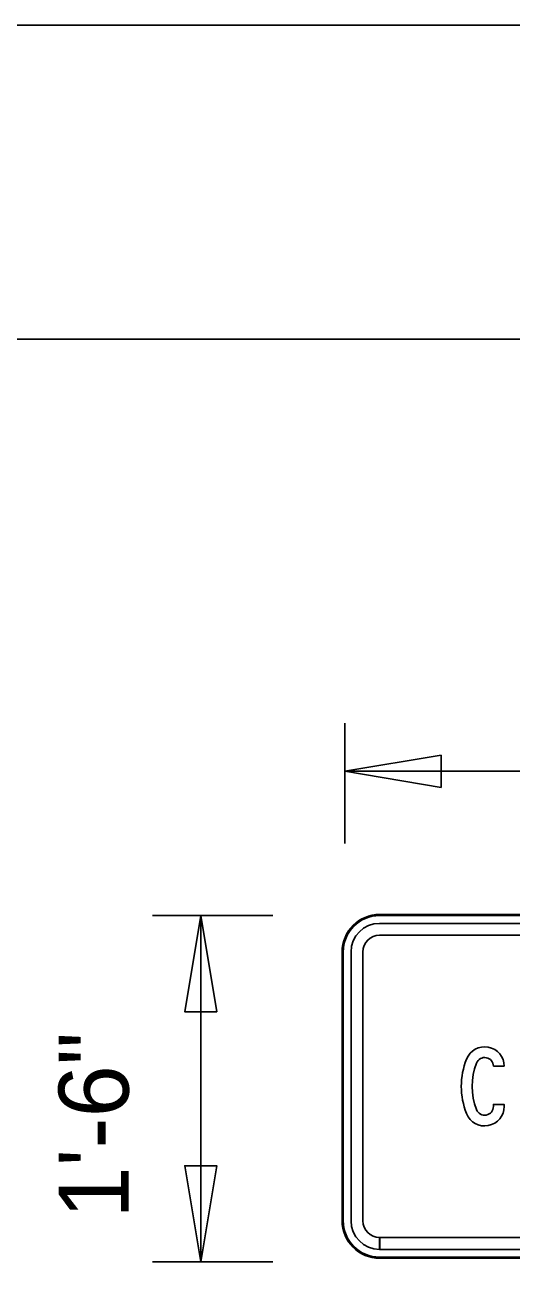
# Model space of a CAD drawing. Extents: x 768137 to 769825, y 651421 to 652521.
# Drawn here: x 769087.4 to 769150.7, y 652123.1 to 652287.3 of the extents above; entities that cross this region are included whole.
import ezdxf

# ---------------------------------------------------------------- set-up
doc = ezdxf.new("R2010")
doc.units = 0
doc.layers.add('Default', color=7, linetype='Continuous')
doc.layers.add('Text', color=7, linetype='Continuous')

msp = doc.modelspace()

# ---------------------------------------------------------------- linework, layer by layer
at = {"layer": 'Default'}
for p, q in [((769128.97, 652180.8), (769128.97, 652196.44)), ((769128.97, 652190.19), (769264.14, 652190.19)), ((769128.97, 652180.8), (769128.97, 652180.8)), ((769257.93, 652171.57), (769133.49, 652171.57)), ((769257.93, 652171.57), (769133.49, 652171.57)), ((769257.93, 652171.57), (769133.49, 652171.57)), ((769257.93, 652171.57), (769133.49, 652171.57)), ((769119.59, 652171.41), (769103.94, 652171.41)), ((769110.2, 652126.36), (769110.2, 652171.41)), ((769119.59, 652171.41), (769119.59, 652171.41)), ((769133.49, 652171.41), (769257.93, 652171.41)), ((769257.93, 652170.4), (769133.49, 652170.4)), ((769257.93, 652170.4), (769133.49, 652170.4)), ((769257.93, 652170.4), (769133.49, 652170.4)), ((769257.93, 652168.85), (769133.49, 652168.85)), ((769133.49, 652168.85), (769257.93, 652168.85)), ((769133.49, 652168.85), (769257.93, 652168.85)), ((769128.59, 652166.68), (769128.59, 652131.72)), ((769128.59, 652166.68), (769128.59, 652131.72)), ((769128.59, 652166.68), (769128.59, 652131.72)), ((769128.59, 652166.68), (769128.59, 652131.72)), ((769128.75, 652131.72), (769128.75, 652166.68)), ((769129.76, 652166.68), (769129.76, 652131.72)), ((769129.76, 652166.68), (769129.76, 652131.72)), ((769129.76, 652166.68), (769129.76, 652131.72)), ((769131.31, 652166.68), (769131.31, 652131.72)), ((769131.31, 652131.72), (769131.31, 652166.68)), ((769131.31, 652131.72), (769131.31, 652166.68)), ((769148.3, 652151.81), (769149.69, 652151.81)), ((769148.3, 652151.81), (769149.69, 652151.81)), ((769148.3, 652151.81), (769149.69, 652151.81)), ((769133.49, 652129.54), (769257.93, 652129.54)), ((769133.49, 652127.99), (769133.49, 652129.54)), ((769133.49, 652127.99), (769133.49, 652129.54)), ((769257.93, 652129.54), (769133.5, 652129.54)), ((769133.5, 652129.54), (769133.5, 652127.99)), ((769257.93, 652129.54), (769133.5, 652129.54)), ((769133.5, 652129.54), (769133.5, 652127.99)), ((769133.49, 652127.99), (769257.93, 652127.99)), ((769133.5, 652127.99), (769257.93, 652127.99)), ((769133.5, 652127.99), (769257.93, 652127.99)), ((769119.59, 652126.36), (769103.94, 652126.36)), ((769119.59, 652126.36), (769119.59, 652126.36)), ((769133.49, 652126.83), (769133.49, 652126.98)), ((769257.93, 652126.98), (769133.49, 652126.98)), ((769133.49, 652126.98), (769133.49, 652126.83)), ((769133.49, 652126.83), (769257.93, 652126.83)), ((769133.49, 652126.83), (769257.93, 652126.83)), ((769133.49, 652126.83), (769257.93, 652126.83)), ((769133.49, 652126.83), (769257.93, 652126.83))]:
    msp.add_line(p, q, dxfattribs=at)
for points in [[(769128.97, 652190.19), (769141.49, 652188.1), (769141.49, 652192.27)], [(769110.2, 652171.41), (769112.29, 652158.9), (769108.11, 652158.9)], [(769110.2, 652126.36), (769112.29, 652138.87), (769108.11, 652138.87)]]:
    msp.add_lwpolyline(points, close=True, dxfattribs=at)
msp.add_lwpolyline([(769149.69, 652146.59), (769149.69, 652146.86), (769148.3, 652146.86), (769148.3, 652146.59)], dxfattribs=at)
msp.add_lwpolyline([(769149.69, 652146.59), (769149.69, 652146.86), (769148.3, 652146.86), (769148.3, 652146.59)], dxfattribs=at)
msp.add_lwpolyline([(769149.69, 652146.59), (769149.69, 652146.86), (769148.3, 652146.86), (769148.3, 652146.59)], dxfattribs=at)
for centre, radius, start, end in [((769133.49, 652166.68), 4.89, 90, 180), ((769133.49, 652166.68), 4.89, 90, 180), ((769133.49, 652166.68), 4.89, 90, 180), ((769133.49, 652166.68), 4.89, 90, 180), ((769133.49, 652166.68), 4.74, 90, 180), ((769133.49, 652166.68), 3.73, 90, 180), ((769133.49, 652166.68), 3.73, 90, 180), ((769133.49, 652166.68), 3.73, 90, 180), ((769133.49, 652166.68), 2.18, 90, 180), ((769133.49, 652166.68), 2.18, 90, 180), ((769133.49, 652166.68), 2.18, 90, 180), ((769147.16, 652151.81), 2.54, 0, 158.4314), ((769147.16, 652151.81), 2.54, 0, 158.4314), ((769147.16, 652151.81), 2.54, 0, 158.4314), ((769153.76, 652149.2), 9.64, 158.4314, 201.5686), ((769153.76, 652149.2), 9.64, 158.4314, 201.5686), ((769153.76, 652149.2), 9.64, 158.4314, 201.5686), ((769153.76, 652149.2), 8.24, 158.4314, 201.5686), ((769153.76, 652149.2), 8.24, 158.4314, 201.5686), ((769153.76, 652149.2), 8.24, 158.4314, 201.5686), ((769147.16, 652151.81), 1.14, 0, 158.4314), ((769147.16, 652151.81), 1.14, 0, 158.4314), ((769147.16, 652151.81), 1.14, 0, 158.4314), ((769147.16, 652146.59), 2.54, 201.5686, 0), ((769147.16, 652146.59), 2.54, 201.5686, 0), ((769147.16, 652146.59), 2.54, 201.5686, 0), ((769147.16, 652146.59), 1.14, 201.5686, 0), ((769147.16, 652146.59), 1.14, 201.5686, 0), ((769147.16, 652146.59), 1.14, 201.5686, 0), ((769133.49, 652131.72), 4.89, 180, 270), ((769133.49, 652131.72), 4.89, 180, 270), ((769133.49, 652131.72), 4.89, 180, 270), ((769133.49, 652131.72), 4.89, 180, 270), ((769133.49, 652131.72), 4.74, 180, 270), ((769133.49, 652131.72), 3.73, 180, 270), ((769133.49, 652131.72), 3.73, 180, 270), ((769133.49, 652131.72), 3.73, 180, 270), ((769133.49, 652131.72), 2.18, 180, 270), ((769133.49, 652131.72), 2.18, 180, 270), ((769133.49, 652131.72), 2.18, 180, 270)]:
    msp.add_arc(centre, radius, start, end, dxfattribs=at)
at = {"layer": 'Text'}
msp.add_line((768955.49, 652246.42), (769456.98, 652246.42), dxfattribs=at)
msp.add_lwpolyline([(768629.35, 652287.25), (769456.98, 652287.25), (769456.98, 651713.27), (768629.35, 651713.27)], close=True, dxfattribs=at)

# ---------------------------------------------------------------- texts
at = {"layer": 'Default'}
msp.add_text('1\'-6"', height=9.124, rotation=90, dxfattribs=at).set_placement((769100.82, 652131.99))

doc.saveas('drawing.dxf')
